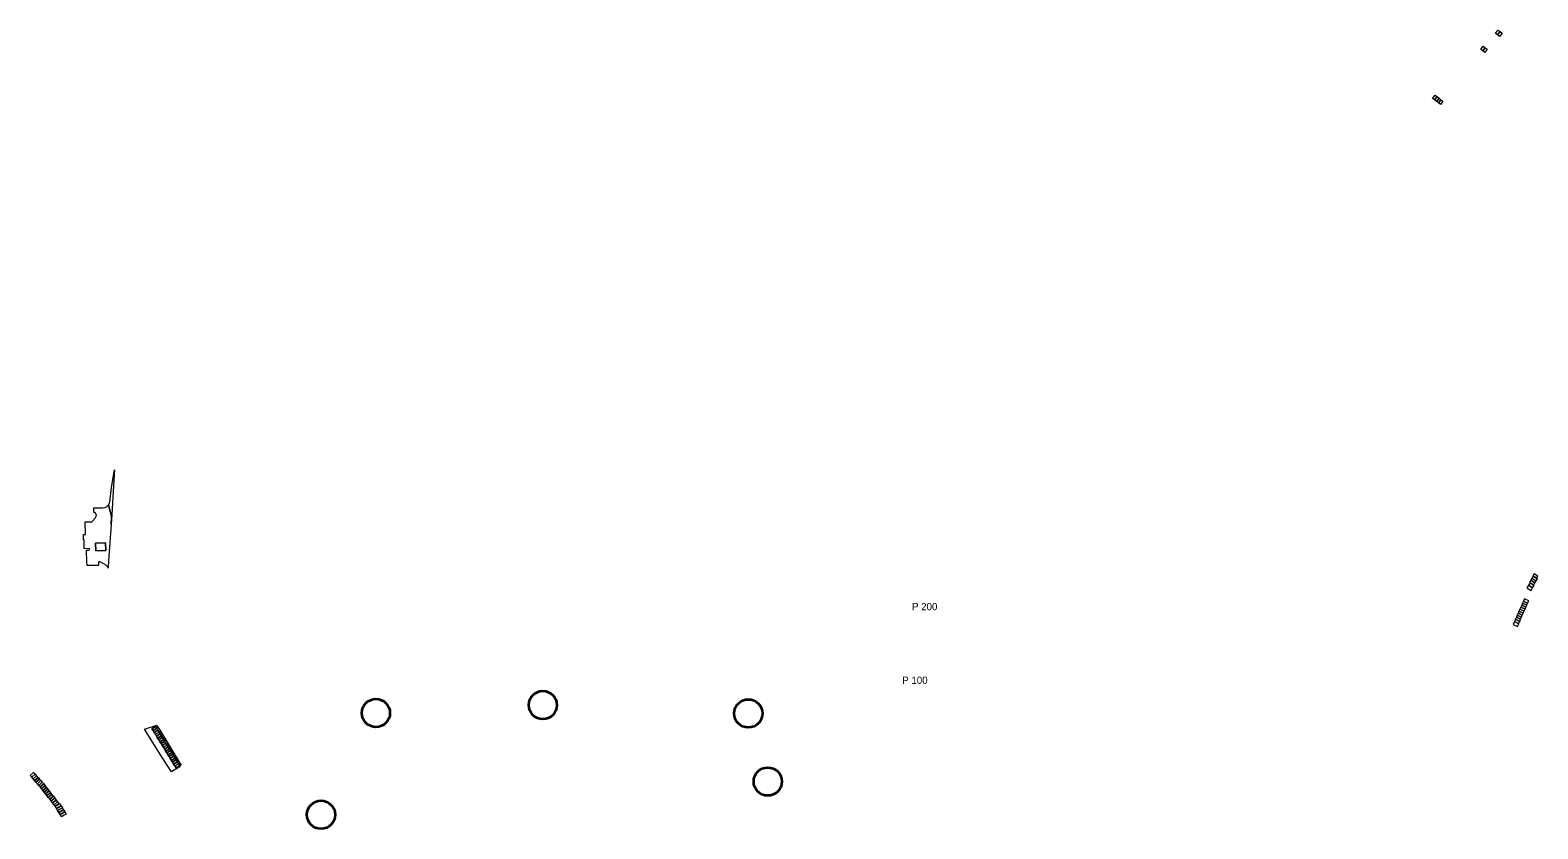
# Model space of a CAD drawing. Extents: x -648438 to -645379, y -1072966 to -1066997.
# Drawn here: x -647948 to -645873, y -1069832 to -1068733 of the extents above; entities that cross this region are included whole.
import ezdxf

# ---------------------------------------------------------------- set-up
doc = ezdxf.new("R2010")
doc.units = 0
doc.header["$LTSCALE"] = 4
doc.layers.add('40', color=7, linetype='Continuous', lineweight=13)
doc.layers.add('56', color=7, linetype='Continuous')

msp = doc.modelspace()

# ---------------------------------------------------------------- linework, layer by layer
at = {"layer": '40'}
for points in [[(-645931.11, -1068737.76), (-645927.9, -1068733.25), (-645925.14, -1068735.32), (-645928.57, -1068739.88)], [(-645928.57, -1068739.88), (-645925.14, -1068735.32), (-645922.38, -1068737.4), (-645925.69, -1068741.97)], [(-645951.68, -1068759.88), (-645948.43, -1068755.37), (-645945.68, -1068757.36), (-645948.95, -1068761.91)], [(-645948.95, -1068761.91), (-645945.68, -1068757.36), (-645942.93, -1068759.35), (-645946.23, -1068763.94)], [(-646017.95, -1068827.09), (-646014.32, -1068822.69), (-646011.73, -1068824.76), (-646015.29, -1068829.21)], [(-646015.29, -1068829.21), (-646011.73, -1068824.76), (-646009.07, -1068826.88), (-646012.63, -1068831.33)], [(-646012.63, -1068831.33), (-646009.07, -1068826.88), (-646006.42, -1068829), (-646009.97, -1068833.45)], [(-646009.97, -1068833.45), (-646006.42, -1068829), (-646003.76, -1068831.12), (-646007.27, -1068835.51)], [(-647840.42, -1069386.51), (-647839.4, -1069384.73), (-647838.79, -1069382.86), (-647836.2, -1069362.68), (-647832.29, -1069338.58), (-647833.65, -1069360.37), (-647836.12, -1069400.05), (-647837, -1069413.65), (-647836.5, -1069402.01), (-647836.7, -1069400.99), (-647837.5, -1069399.15)], [(-647858.31, -1069439.45), (-647858.07, -1069449.67), (-647844.4, -1069449.36), (-647844.66, -1069439.07)], [(-647858.31, -1069439.45), (-647844.66, -1069439.07), (-647844.4, -1069449.36), (-647858.07, -1069449.67)], [(-647841.11, -1069473.41), (-647840.92, -1069473.84), (-647840.77, -1069471.49), (-647842.43, -1069471.64)], [(-645875.39, -1069491.3), (-645873.59, -1069488.42), (-645874.82, -1069487.65), (-645879.31, -1069484.84), (-645881.11, -1069487.72)], [(-645874.82, -1069487.65), (-645873.05, -1069484.82), (-645877.97, -1069481.73), (-645879.74, -1069484.57), (-645879.31, -1069484.84)], [(-645882.42, -1069504.44), (-645880.22, -1069500.92), (-645885.96, -1069497.27), (-645888.1, -1069500.82)], [(-645880.22, -1069500.92), (-645878.07, -1069497.47), (-645878.91, -1069496.94), (-645883.83, -1069493.87), (-645885.96, -1069497.27)], [(-645878.91, -1069496.94), (-645877.09, -1069494.01), (-645882.81, -1069490.44), (-645884.64, -1069493.36), (-645883.83, -1069493.87)], [(-645877.09, -1069494.01), (-645875.39, -1069491.3), (-645881.11, -1069487.72), (-645882.81, -1069490.44)], [(-645890.73, -1069530.08), (-645889.51, -1069527.34), (-645895.31, -1069524.75), (-645896.53, -1069527.49)], [(-645889.51, -1069527.34), (-645888.32, -1069524.69), (-645894.12, -1069522.1), (-645895.31, -1069524.75)], [(-645888.32, -1069524.69), (-645887.1, -1069521.95), (-645892.9, -1069519.36), (-645894.12, -1069522.1)], [(-645887.1, -1069521.95), (-645885.66, -1069518.71), (-645891.46, -1069516.12), (-645892.9, -1069519.36)], [(-645901.19, -1069554.15), (-645899.43, -1069550.12), (-645905.39, -1069547.35), (-645907.18, -1069551.37)], [(-645899.43, -1069550.12), (-645898.59, -1069548.21), (-645898.02, -1069546.92), (-645903.94, -1069544.11), (-645905.39, -1069547.35)], [(-645898.02, -1069546.92), (-645896.86, -1069543.82), (-645902.66, -1069541.24), (-645903.94, -1069544.11)], [(-645896.86, -1069543.82), (-645895.64, -1069541.08), (-645901.44, -1069538.5), (-645902.66, -1069541.24)], [(-645895.64, -1069541.08), (-645894.44, -1069538.39), (-645900.23, -1069535.8), (-645901.44, -1069538.5)], [(-645894.44, -1069538.39), (-645893.21, -1069535.65), (-645899.01, -1069533.06), (-645900.23, -1069535.8)], [(-645893.21, -1069535.65), (-645891.95, -1069532.82), (-645897.75, -1069530.23), (-645899.01, -1069533.06)], [(-645891.95, -1069532.82), (-645890.73, -1069530.08), (-645896.53, -1069527.49), (-645897.75, -1069530.23)], [(-647790.88, -1069695.49), (-647774.11, -1069689.64), (-647772.13, -1069692.89), (-647770.38, -1069695.75), (-647740.74, -1069744.24), (-647742.36, -1069746.93), (-647752.32, -1069752.95), (-647753.7, -1069753.9), (-647766.73, -1069734.5)], [(-647780.72, -1069694.71), (-647775.59, -1069691.55), (-647774.02, -1069694.11), (-647779.15, -1069697.27)], [(-647779.15, -1069697.27), (-647774.02, -1069694.11), (-647772.45, -1069696.66), (-647777.58, -1069699.82)], [(-647777.58, -1069699.82), (-647772.45, -1069696.66), (-647770.87, -1069699.22), (-647776.01, -1069702.38)], [(-647776.01, -1069702.38), (-647770.87, -1069699.22), (-647769.3, -1069701.78), (-647774.44, -1069704.93)], [(-647774.44, -1069704.93), (-647769.3, -1069701.78), (-647767.72, -1069704.33), (-647772.87, -1069707.49)], [(-647772.87, -1069707.49), (-647767.72, -1069704.33), (-647766.15, -1069706.89), (-647771.31, -1069710.04)], [(-647771.31, -1069710.04), (-647766.15, -1069706.89), (-647764.57, -1069709.45), (-647769.74, -1069712.6)], [(-647769.74, -1069712.6), (-647764.57, -1069709.45), (-647763, -1069712.01), (-647768.17, -1069715.15)], [(-647768.17, -1069715.15), (-647763, -1069712.01), (-647761.42, -1069714.57), (-647766.6, -1069717.7)], [(-647766.6, -1069717.7), (-647761.42, -1069714.57), (-647759.85, -1069717.12), (-647765.03, -1069720.26)], [(-647765.03, -1069720.26), (-647759.85, -1069717.12), (-647758.28, -1069719.68), (-647763.46, -1069722.81)], [(-647763.46, -1069722.81), (-647758.28, -1069719.68), (-647756.7, -1069722.24), (-647761.9, -1069725.37)], [(-647761.9, -1069725.37), (-647756.7, -1069722.24), (-647755.13, -1069724.8), (-647760.33, -1069727.92)], [(-647760.33, -1069727.92), (-647755.13, -1069724.8), (-647753.55, -1069727.35), (-647758.76, -1069730.48)], [(-647758.76, -1069730.48), (-647753.55, -1069727.35), (-647751.98, -1069729.91), (-647757.19, -1069733.03)], [(-647757.19, -1069733.03), (-647751.98, -1069729.91), (-647750.35, -1069732.55), (-647755.57, -1069735.67)], [(-647755.57, -1069735.67), (-647750.35, -1069732.55), (-647748.78, -1069735.11), (-647754, -1069738.22)], [(-647948.35, -1069759.15), (-647943.52, -1069754.88), (-647942.14, -1069756.45), (-647941.41, -1069757.28), (-647946.23, -1069761.55)], [(-647754, -1069738.22), (-647748.78, -1069735.11), (-647747.18, -1069737.71), (-647752.41, -1069740.82)], [(-647752.41, -1069740.82), (-647747.18, -1069737.71), (-647745.58, -1069740.31), (-647750.81, -1069743.42)], [(-647750.81, -1069743.42), (-647745.58, -1069740.31), (-647744.03, -1069742.83), (-647749.27, -1069745.93)], [(-647749.27, -1069745.93), (-647744.03, -1069742.83), (-647742.48, -1069745.34), (-647747.73, -1069748.44)], [(-647946.23, -1069761.55), (-647941.41, -1069757.28), (-647939.43, -1069759.53), (-647944.24, -1069763.79)], [(-647944.24, -1069763.79), (-647939.43, -1069759.53), (-647937.47, -1069761.75), (-647942.29, -1069766)], [(-647942.29, -1069766), (-647937.47, -1069761.75), (-647935.53, -1069763.96), (-647940.33, -1069768.21)], [(-647940.33, -1069768.21), (-647935.53, -1069763.96), (-647933.58, -1069766.18), (-647938.38, -1069770.42)], [(-647938.38, -1069770.42), (-647933.58, -1069766.18), (-647931.63, -1069768.39), (-647936.43, -1069772.63)], [(-647936.43, -1069772.63), (-647931.63, -1069768.39), (-647929.62, -1069770.68), (-647934.69, -1069774.59)], [(-647934.69, -1069774.59), (-647929.62, -1069770.68), (-647927.69, -1069773.17), (-647932.77, -1069777.08)], [(-647932.77, -1069777.08), (-647927.69, -1069773.17), (-647925.85, -1069775.54), (-647930.91, -1069779.5)], [(-647930.91, -1069779.5), (-647925.85, -1069775.54), (-647924.04, -1069777.87), (-647929.14, -1069781.8)], [(-647929.14, -1069781.8), (-647924.04, -1069777.87), (-647922.17, -1069780.28), (-647927.34, -1069784.14)], [(-647927.34, -1069784.14), (-647922.17, -1069780.28), (-647920.21, -1069782.81), (-647925.33, -1069786.75)], [(-647925.33, -1069786.75), (-647920.21, -1069782.81), (-647918.31, -1069785.26), (-647923.43, -1069789.21)], [(-647923.43, -1069789.21), (-647918.31, -1069785.26), (-647916.41, -1069787.71), (-647921.28, -1069791.59), (-647921.48, -1069791.74)], [(-647921.28, -1069791.59), (-647916.41, -1069787.71), (-647914.45, -1069790.24), (-647919.35, -1069794.14)], [(-647919.35, -1069794.14), (-647914.45, -1069790.24), (-647912.46, -1069792.81), (-647917.38, -1069796.72)], [(-647917.38, -1069796.72), (-647912.46, -1069792.81), (-647910.53, -1069795.3), (-647915.44, -1069799.27)], [(-647915.44, -1069799.27), (-647910.53, -1069795.3), (-647908.28, -1069798.2), (-647913.84, -1069801.36)], [(-647913.84, -1069801.36), (-647908.28, -1069798.2), (-647907.46, -1069797.74), (-647905.71, -1069800.64), (-647906.6, -1069801.16), (-647912.12, -1069804.35)], [(-647912.12, -1069804.35), (-647906.6, -1069801.16), (-647905.71, -1069800.64), (-647904.01, -1069803.47), (-647904.97, -1069804.03), (-647910.48, -1069807.21)], [(-647910.48, -1069807.21), (-647904.97, -1069804.03), (-647904.01, -1069803.47), (-647902.36, -1069806.2), (-647903.39, -1069806.81), (-647908.85, -1069810.03)], [(-647908.85, -1069810.03), (-647903.39, -1069806.81), (-647902.36, -1069806.2), (-647900.63, -1069809.06), (-647901.74, -1069809.72), (-647907.16, -1069812.97)], [(-647907.16, -1069812.97), (-647901.74, -1069809.72), (-647900.63, -1069809.06), (-647898.71, -1069812.26), (-647899.91, -1069812.94), (-647901.54, -1069813.87), (-647905.39, -1069816.05), (-647905.87, -1069815.22)]]:
    msp.add_lwpolyline(points, close=True, dxfattribs=at)
for points in [[(-647875.06, -1069434.93), (-647875.04, -1069427.38), (-647872.39, -1069427.33), (-647872.43, -1069409.75), (-647862.87, -1069409.82), (-647862.33, -1069408.98), (-647859.06, -1069404.7), (-647857.89, -1069403.04), (-647857.24, -1069401.16), (-647857.63, -1069399.17), (-647858.49, -1069398.05), (-647859.78, -1069397.17), (-647860.67, -1069396.92), (-647860.52, -1069390.72), (-647848.24, -1069390.65), (-647845.25, -1069390.07), (-647843.41, -1069389.23), (-647841.81, -1069387.99), (-647840.42, -1069386.51), (-647837.5, -1069399.15), (-647836.7, -1069400.99), (-647836.5, -1069402.01), (-647837, -1069413.65), (-647839.83, -1069457.08), (-647840.77, -1069471.49), (-647842.43, -1069471.64), (-647843.01, -1069470.87), (-647845.27, -1069468.87), (-647847.93, -1069467.23), (-647852.6, -1069465.08), (-647853.16, -1069465.01), (-647853.73, -1069465.17), (-647854.28, -1069466.25), (-647854.2, -1069470.11), (-647865.34, -1069470.12), (-647866.54, -1069470.15), (-647869.99, -1069470.17), (-647870.2, -1069465.31), (-647871, -1069448.98), (-647867.45, -1069448.89)], [(-647867.45, -1069448.89), (-647866.56, -1069448.46), (-647866, -1069447.66), (-647866.87, -1069446.78), (-647873.91, -1069446.89), (-647874, -1069442.09), (-647874.04, -1069439.74), (-647874.14, -1069434.94), (-647875.06, -1069434.93)], [(-647769.3, -1069701.78), (-647770.87, -1069699.22), (-647772.45, -1069696.66), (-647774.02, -1069694.11), (-647775.59, -1069691.55), (-647780.72, -1069694.71)], [(-647780.72, -1069694.71), (-647779.15, -1069697.27), (-647777.58, -1069699.82), (-647776.01, -1069702.38), (-647774.44, -1069704.93), (-647772.87, -1069707.49), (-647771.31, -1069710.04), (-647769.74, -1069712.6), (-647768.17, -1069715.15), (-647766.6, -1069717.7), (-647765.03, -1069720.26), (-647763.46, -1069722.81), (-647761.9, -1069725.37), (-647760.33, -1069727.92), (-647758.76, -1069730.48), (-647757.19, -1069733.03), (-647755.57, -1069735.67), (-647754, -1069738.22), (-647752.41, -1069740.82), (-647750.81, -1069743.42), (-647749.27, -1069745.93), (-647747.73, -1069748.44), (-647742.48, -1069745.34), (-647744.03, -1069742.83), (-647745.58, -1069740.31), (-647747.18, -1069737.71), (-647748.78, -1069735.11), (-647750.35, -1069732.55), (-647751.98, -1069729.91), (-647753.55, -1069727.35), (-647755.13, -1069724.8), (-647756.7, -1069722.24), (-647758.28, -1069719.68), (-647759.85, -1069717.12), (-647761.42, -1069714.57), (-647763, -1069712.01), (-647764.57, -1069709.45), (-647766.15, -1069706.89), (-647767.72, -1069704.33), (-647769.3, -1069701.78)]]:
    msp.add_lwpolyline(points, dxfattribs=at)
at = {"layer": '40', "lineweight": 35}
for centre in [(-647242.671, -1069662.134), (-647472.467, -1069673.052), (-646959.82, -1069673.705), (-646932.984, -1069767.354), (-647547.998, -1069813.078)]:
    msp.add_circle(centre, 19.412, dxfattribs=at)

# ---------------------------------------------------------------- texts
at = {"layer": '56'}
for s, p in [('P 200', (-646734.541, -1069531.64)), ('P 100', (-646747.94, -1069632.939))]:
    msp.add_text(s, height=10, dxfattribs=at).set_placement(p)

doc.saveas('drawing.dxf')
